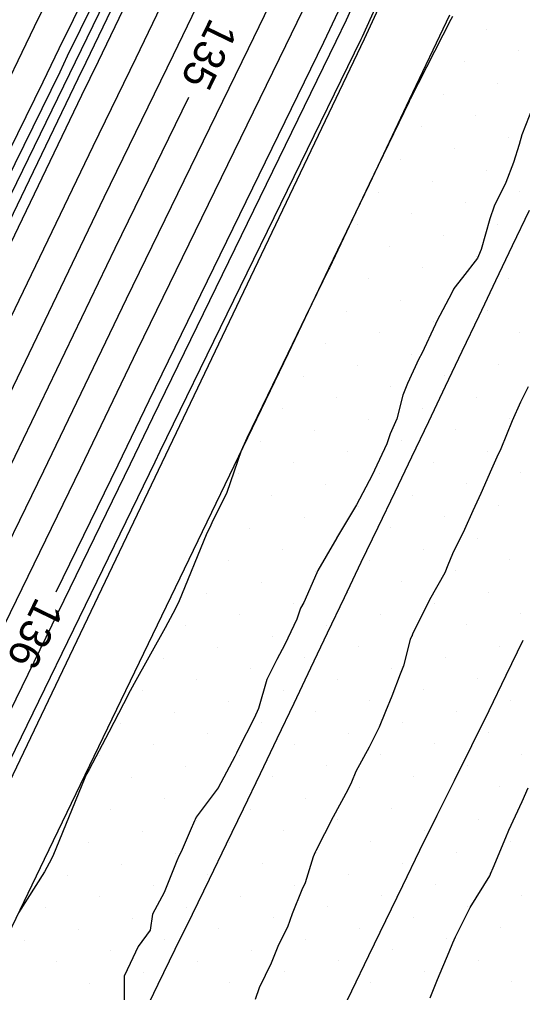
# Model space of a CAD drawing. Extents: x 2354170 to 2357230, y 866100 to 868290.
# Drawn here: x 2355371.3 to 2355403.5, y 866398.3 to 866460.6 of the extents above; entities that cross this region are included whole.
import ezdxf

# ---------------------------------------------------------------- set-up
doc = ezdxf.new("R2010")
doc.units = 0
for name, color, linetype in [('Default', 7, 'Continuous'), ('DTM Contours Major', 7, 'Continuous'), ('DTM Contours Major Text', 7, 'Continuous'), ('DTM Contours Minor', 7, 'Continuous'), ('Exist DTM Breakline', 7, 'Continuous'), ('Exist DTM Scan Elevation Point', 7, 'Continuous'), ('Exist Roads EOP', 7, 'Continuous'), ('PH Exist DTM Breakline', 7, 'Continuous')]:
    doc.layers.add(name, color=color, linetype=linetype)

msp = doc.modelspace()

# ---------------------------------------------------------------- linework, layer by layer
at = {"layer": 'Default'}
for points in [[(2355433.274, 866592.65), (2355424.806, 866571.951), (2355424.411, 866571.12), (2355422.868, 866571.668), (2355420.162, 866565.925), (2355419.736, 866563.735), (2355420.105, 866562.501), (2355413.621, 866548.376), (2355412.407, 866545.801), (2355402.074, 866526.578), (2355397.826, 866518.933), (2355392.022, 866504.988), (2355390.529, 866502.372), (2355387.356, 866494.737), (2355378.915, 866474.238), (2355377.709, 866471.334), (2355372.225, 866460.176), (2355369.578, 866454.696), (2355359.039, 866433.252), (2355357.778, 866430.64), (2355352.681, 866420.776), (2355349.804, 866415.162), (2355338.927, 866394.115), (2355337.24, 866390.821)], [(2355336.64, 866372.256), (2355339.663, 866378.549), (2355343.753, 866388.56), (2355346.394, 866394.067), (2355357.545, 866415.181), (2355357.799, 866415.7), (2355362.943, 866425.442), (2355365.741, 866431.183), (2355376.003, 866452.523), (2355378.759, 866458.177), (2355384.09, 866469.263), (2355386.61, 866474.85), (2355397.375, 866495.699), (2355400.619, 866502.876), (2355407.827, 866516.962), (2355410.624, 866522.841), (2355419.192, 866542.505), (2355426.718, 866555.797), (2355429.354, 866561.334), (2355429.604, 866563.56), (2355430.426, 866564.821), (2355431.528, 866567.132), (2355430.551, 866568.321), (2355442.375, 866586.643)], [(2355337.287, 866368.659), (2355341.828, 866378.112), (2355345.253, 866386.495), (2355349.543, 866395.439), (2355358.93, 866413.212), (2355359.335, 866414.044), (2355363.665, 866422.241), (2355368.111, 866431.366), (2355376.717, 866449.262), (2355381.159, 866458.376), (2355385.613, 866467.639), (2355389.708, 866476.715), (2355398.736, 866494.201), (2355403.429, 866504.581), (2355409.497, 866516.439), (2355413.331, 866524.5), (2355420.561, 866541.092), (2355426.912, 866552.308), (2355431.145, 866561.201), (2355431.357, 866563.085), (2355432.052, 866564.152), (2355433.804, 866567.826), (2355432.973, 866568.836), (2355443.028, 866584.416)], [(2355338.581, 866361.464), (2355346.158, 866377.236), (2355348.253, 866382.363), (2355355.841, 866398.182), (2355361.699, 866409.275), (2355362.409, 866410.731), (2355365.108, 866415.841), (2355372.851, 866431.732), (2355378.145, 866442.741), (2355385.959, 866458.773), (2355388.661, 866464.392), (2355395.902, 866480.443), (2355401.46, 866491.207), (2355409.048, 866507.992), (2355412.835, 866515.394), (2355418.746, 866527.817), (2355423.299, 866538.266), (2355427.298, 866545.329), (2355434.727, 866560.935), (2355434.862, 866562.135), (2355435.305, 866562.815), (2355438.356, 866569.213), (2355437.818, 866569.868), (2355444.332, 866579.962)], [(2355406.465, 866530.834), (2355402.54, 866523.532), (2355399.868, 866518.725), (2355393.049, 866502.339), (2355392.222, 866500.891), (2355390.465, 866496.663), (2355380.621, 866472.756), (2355380.168, 866471.665), (2355373.822, 866458.755), (2355372.795, 866456.627), (2355364.665, 866440.085)], [(2355416.208, 866514.42), (2355416.174, 866514.348), (2355414.668, 866511.403), (2355404.183, 866488.212), (2355402.097, 866484.172), (2355391.708, 866461.146), (2355390.759, 866459.171), (2355379.573, 866436.22), (2355377.591, 866432.097), (2355373.624, 866423.956)], [(2355405.194, 866486.036), (2355393.232, 866459.522), (2355393.159, 866459.369), (2355380.287, 866432.959), (2355379.961, 866432.28), (2355367.272, 866406.241), (2355367.019, 866405.761), (2355365.854, 866403.37), (2355365.287, 866402.297), (2355352.753, 866376.167), (2355352.653, 866375.923), (2355341.387, 866352.472), (2355340.659, 866350.872), (2355340.623, 866350.802), (2355340.589, 866350.736), (2355340.557, 866350.674), (2355340.528, 866350.607), (2355340.495, 866350.531), (2355331.001, 866327.562)], [(2355336.417, 866351.091), (2355339.228, 866357.866), (2355348.323, 866376.799), (2355349.753, 866380.298), (2355358.989, 866399.554), (2355363.084, 866407.307), (2355363.946, 866409.074), (2355365.829, 866412.641), (2355375.221, 866431.914), (2355378.859, 866439.481), (2355388.359, 866458.972), (2355390.184, 866462.769)], [(2355334.401, 866372.018), (2355335.993, 866375.854), (2355337.498, 866378.987), (2355342.253, 866390.626), (2355343.246, 866392.695), (2355356.16, 866417.149), (2355356.262, 866417.357), (2355362.221, 866428.642), (2355363.371, 866431), (2355375.289, 866455.784), (2355376.359, 866457.979), (2355378.218, 866461.844)], [(2355399.022, 866460.838), (2355398.921, 866460.632), (2355396.309, 866455.526), (2355396.293, 866455.496), (2355396.273, 866455.455), (2355396.24, 866455.379), (2355394.259, 866451.292), (2355393.678, 866450.087), (2355392.398, 866447.393), (2355391.138, 866444.731), (2355391.102, 866444.657), (2355391.097, 866444.646), (2355391.09, 866444.631), (2355389.617, 866441.586), (2355388.485, 866439.24), (2355385.844, 866433.828), (2355385.496, 866433.015), (2355384.563, 866430.346), (2355383.61, 866428.394), (2355383.479, 866428.103), (2355383.291, 866427.726), (2355381.476, 866423.294), (2355381.122, 866422.597), (2355380.623, 866421.676), (2355378.638, 866418.108), (2355378.389, 866417.632), (2355377.958, 866416.807), (2355377.011, 866414.986), (2355375.746, 866412.595), (2355375.55, 866412.222), (2355375.518, 866412.158), (2355375.478, 866412.071), (2355373.427, 866407.034), (2355373.195, 866406.6), (2355372.892, 866406.042), (2355371.232, 866403.418)], [(2355338.298, 866365.818), (2355343.993, 866377.674), (2355346.753, 866384.429), (2355352.692, 866396.81), (2355360.315, 866411.244), (2355360.872, 866412.387), (2355364.386, 866419.041), (2355370.481, 866431.549), (2355377.431, 866446.002), (2355382.14, 866455.663)], [(2355404.172, 866455.045), (2355403.459, 866453.255), (2355403.287, 866452.633), (2355402.935, 866451.485), (2355402.45, 866450.189), (2355401.702, 866448.677), (2355401.415, 866447.876), (2355400.857, 866445.901), (2355400.697, 866445.491), (2355400.631, 866445.355), (2355399.667, 866444.103), (2355399.111, 866443.406), (2355399.083, 866443.343), (2355398.783, 866442.767), (2355398.032, 866441.308), (2355397.944, 866441.129), (2355397.064, 866439.234), (2355396.866, 866438.896), (2355396.144, 866437.332), (2355395.846, 866436.573), (2355395.457, 866435.051), (2355395.041, 866434.108), (2355394.816, 866433.454), (2355394.03, 866431.779), (2355393.877, 866431.458), (2355392.873, 866429.547), (2355391.6, 866427.415), (2355391.592, 866427.397), (2355391.473, 866427.187), (2355390.405, 866425.337), (2355390.342, 866425.199), (2355389.497, 866423.296), (2355389.286, 866422.928), (2355389.048, 866422.228), (2355388.279, 866420.596), (2355387.77, 866419.646), (2355387.141, 866418.351), (2355386.605, 866416.507), (2355386.333, 866415.888), (2355385.329, 866413.914), (2355385.189, 866413.647), (2355385.08, 866413.43), (2355384.027, 866411.418), (2355382.613, 866409.535), (2355382.553, 866409.396), (2355382.497, 866409.296), (2355382.22, 866408.671), (2355381.651, 866407.31), (2355381.524, 866407.079), (2355381.377, 866406.748), (2355380.556, 866404.722), (2355379.803, 866403.335), (2355379.67, 866402.311), (2355378.888, 866401.25), (2355378.382, 866400.165), (2355378.004, 866399.361), (2355377.992, 866397.749)]]:
    msp.add_lwpolyline(points, dxfattribs=at)
at = {"layer": 'DTM Contours Major'}
msp.add_lwpolyline([(2355338.298, 866365.818), (2355343.993, 866377.674), (2355346.753, 866384.429), (2355352.692, 866396.81), (2355360.315, 866411.244), (2355360.872, 866412.387), (2355364.386, 866419.041), (2355370.481, 866431.549), (2355377.431, 866446.002), (2355382.14, 866455.663)], dxfattribs=at)
at = {"layer": 'DTM Contours Minor'}
for points in [[(2355399.763, 866516.766), (2355393.392, 866501.457), (2355392.787, 866500.397), (2355391.502, 866497.306), (2355381.19, 866472.262), (2355380.988, 866471.775), (2355374.355, 866458.281), (2355373.867, 866457.271), (2355361.144, 866431.383), (2355360.874, 866430.823), (2355354.726, 866418.925), (2355354.15, 866417.801), (2355340.943, 866392.246), (2355340.66, 866391.694), (2355334.233, 866380.026), (2355333.119, 866377.75), (2355319.997, 866353.661), (2355315.443, 866345.205), (2355313.17, 866340.539), (2355311.526, 866337.459)], [(2355407.018, 866492.981), (2355404.637, 866487.713), (2355403.129, 866484.793), (2355392.216, 866460.604), (2355391.559, 866459.237), (2355379.811, 866435.133), (2355378.381, 866432.158), (2355366.791, 866408.374), (2355365.995, 866406.866), (2355364.93, 866404.683), (2355363.188, 866401.383), (2355351.753, 866377.544), (2355351.21, 866376.215), (2355340.091, 866353.07), (2355339.164, 866350.837), (2355338.86, 866350.045), (2355327.207, 866324.238), (2355326.871, 866323.38), (2355321.752, 866312.104)], [(2355308.331, 866310.232), (2355311.374, 866316.937), (2355319.426, 866337.506), (2355322.028, 866343.268), (2355325.427, 866352.109), (2355335.777, 866377.053), (2355336.776, 866379.133), (2355341.753, 866391.314), (2355342.196, 866392.238), (2355355.699, 866417.805), (2355355.75, 866417.909), (2355361.981, 866429.708), (2355362.581, 866430.939), (2355375.051, 866456.87), (2355375.559, 866457.912), (2355382.058, 866471.427), (2355382.481, 866472.365), (2355392.371, 866491.519)], [(2355403.874, 866437.102), (2355403.379, 866436.122), (2355402.851, 866434.936), (2355402.12, 866433.137), (2355401.856, 866432.596), (2355401.526, 866431.828), (2355400.833, 866430.276), (2355400.326, 866429.164), (2355399.792, 866427.967), (2355399.022, 866426.403), (2355398.727, 866425.674), (2355398.539, 866425.192), (2355397.543, 866423.46), (2355396.462, 866421.259), (2355396.434, 866421.196), (2355396.317, 866420.917), (2355395.883, 866419.239), (2355395.673, 866418.701), (2355395.133, 866417.282), (2355394.742, 866416.32), (2355394.32, 866415.312), (2355393.69, 866414.018), (2355392.84, 866412.467), (2355392.547, 866411.777), (2355392.322, 866411.297), (2355391.378, 866409.553), (2355390.268, 866407.379), (2355390.24, 866407.308), (2355390.106, 866406.997), (2355389.583, 866405.327), (2355389.379, 866404.88), (2355388.765, 866403.357), (2355388.458, 866402.492), (2355387.884, 866401.371), (2355387.406, 866400.19), (2355386.641, 866398.613), (2355386.393, 866397.863)], [(2355397.596, 866397.975), (2355398.058, 866399.138), (2355398.802, 866400.911), (2355399.036, 866401.489), (2355399.211, 866401.876), (2355400.153, 866403.747), (2355401.416, 866405.793), (2355401.46, 866405.88), (2355401.485, 866405.947), (2355401.627, 866406.288), (2355402.433, 866408.234), (2355402.627, 866408.706), (2355403.485, 866410.536), (2355403.876, 866411.427)]]:
    msp.add_lwpolyline(points, dxfattribs=at)
at = {"layer": 'Exist DTM Breakline'}
for points in [[(2355379.083, 866396.585), (2355380.175, 866398.833), (2355381.272, 866401.08), (2355382.368, 866403.327), (2355383.464, 866405.574), (2355384.557, 866407.822), (2355385.638, 866410.076), (2355386.719, 866412.331), (2355387.8, 866414.585), (2355388.88, 866416.84), (2355389.955, 866419.097), (2355391.03, 866421.354), (2355392.105, 866423.611), (2355393.181, 866425.867), (2355394.262, 866428.121), (2355395.343, 866430.376), (2355396.424, 866432.63), (2355397.503, 866434.885), (2355398.577, 866437.142), (2355399.651, 866439.4), (2355400.725, 866441.657), (2355401.8, 866443.915), (2355402.877, 866446.171), (2355403.954, 866448.427)], [(2355391.48, 866396.171), (2355392.57, 866398.421), (2355393.661, 866400.67), (2355394.751, 866402.92), (2355395.842, 866405.17), (2355396.932, 866407.419), (2355398.039, 866409.661), (2355399.152, 866411.9), (2355400.264, 866414.138), (2355401.374, 866416.378), (2355402.459, 866418.631), (2355403.543, 866420.884)]]:
    msp.add_lwpolyline(points, dxfattribs=at)
at = {"layer": 'Exist DTM Scan Elevation Point'}
for p, q in [((2355401.198, 866460.01), (2355401.198, 866460.01)), ((2355403.283, 866458.631), (2355403.283, 866458.631)), ((2355399.819, 866457.925), (2355399.819, 866457.925)), ((2355401.904, 866456.546), (2355401.904, 866456.546)), ((2355398.439, 866455.84), (2355398.439, 866455.84)), ((2355400.524, 866454.461), (2355400.524, 866454.461)), ((2355397.06, 866453.755), (2355397.06, 866453.755)), ((2355402.609, 866453.082), (2355402.609, 866453.082)), ((2355399.145, 866452.376), (2355399.145, 866452.376)), ((2355395.681, 866451.67), (2355395.681, 866451.67)), ((2355401.23, 866450.997), (2355401.23, 866450.997)), ((2355397.766, 866450.291), (2355397.766, 866450.291)), ((2355394.301, 866449.585), (2355394.301, 866449.585)), ((2355403.315, 866449.617), (2355403.315, 866449.617)), ((2355399.851, 866448.912), (2355399.851, 866448.912)), ((2355396.386, 866448.206), (2355396.386, 866448.206)), ((2355392.922, 866447.5), (2355392.922, 866447.5)), ((2355401.936, 866447.532), (2355401.936, 866447.532)), ((2355398.471, 866446.827), (2355398.471, 866446.827)), ((2355395.007, 866446.121), (2355395.007, 866446.121)), ((2355400.556, 866445.447), (2355400.556, 866445.447)), ((2355397.092, 866444.742), (2355397.092, 866444.742)), ((2355393.627, 866444.036), (2355393.627, 866444.036)), ((2355402.641, 866444.068), (2355402.641, 866444.068)), ((2355399.177, 866443.362), (2355399.177, 866443.362)), ((2355395.712, 866442.657), (2355395.712, 866442.657)), ((2355392.248, 866441.951), (2355392.248, 866441.951)), ((2355401.262, 866441.983), (2355401.262, 866441.983)), ((2355397.797, 866441.277), (2355397.797, 866441.277)), ((2355394.333, 866440.572), (2355394.333, 866440.572)), ((2355403.347, 866440.603), (2355403.347, 866440.603)), ((2355390.868, 866439.866), (2355390.868, 866439.866)), ((2355396.418, 866439.192), (2355396.418, 866439.192)), ((2355401.967, 866438.518), (2355401.967, 866438.518)), ((2355392.953, 866438.487), (2355392.953, 866438.487)), ((2355389.489, 866437.781), (2355389.489, 866437.781)), ((2355398.503, 866437.813), (2355398.503, 866437.813)), ((2355395.038, 866437.107), (2355395.038, 866437.107)), ((2355391.574, 866436.402), (2355391.574, 866436.402)), ((2355400.588, 866436.433), (2355400.588, 866436.433)), ((2355388.11, 866435.696), (2355388.11, 866435.696)), ((2355397.123, 866435.728), (2355397.123, 866435.728)), ((2355393.659, 866435.022), (2355393.659, 866435.022)), ((2355402.673, 866435.054), (2355402.673, 866435.054)), ((2355390.195, 866434.317), (2355390.195, 866434.317)), ((2355399.208, 866434.348), (2355399.208, 866434.348)), ((2355386.73, 866433.611), (2355386.73, 866433.611)), ((2355395.744, 866433.643), (2355395.744, 866433.643)), ((2355392.28, 866432.937), (2355392.28, 866432.937)), ((2355401.293, 866432.969), (2355401.293, 866432.969)), ((2355388.815, 866432.232), (2355388.815, 866432.232)), ((2355397.829, 866432.263), (2355397.829, 866432.263)), ((2355385.351, 866431.526), (2355385.351, 866431.526)), ((2355394.364, 866431.558), (2355394.364, 866431.558)), ((2355403.378, 866431.589), (2355403.378, 866431.589)), ((2355390.9, 866430.852), (2355390.9, 866430.852)), ((2355399.914, 866430.884), (2355399.914, 866430.884)), ((2355387.436, 866430.147), (2355387.436, 866430.147)), ((2355396.449, 866430.178), (2355396.449, 866430.178)), ((2355392.985, 866429.473), (2355392.985, 866429.473)), ((2355401.999, 866429.504), (2355401.999, 866429.504)), ((2355389.521, 866428.767), (2355389.521, 866428.767)), ((2355398.534, 866428.799), (2355398.534, 866428.799)), ((2355386.056, 866428.062), (2355386.056, 866428.062)), ((2355395.07, 866428.093), (2355395.07, 866428.093)), ((2355391.606, 866427.388), (2355391.606, 866427.388)), ((2355400.619, 866427.419), (2355400.619, 866427.419)), ((2355388.141, 866426.682), (2355388.141, 866426.682)), ((2355397.155, 866426.714), (2355397.155, 866426.714)), ((2355384.677, 866425.977), (2355384.677, 866425.977)), ((2355393.691, 866426.008), (2355393.691, 866426.008)), ((2355402.704, 866426.04), (2355402.704, 866426.04)), ((2355390.226, 866425.303), (2355390.226, 866425.303)), ((2355399.24, 866425.334), (2355399.24, 866425.334)), ((2355386.762, 866424.597), (2355386.762, 866424.597)), ((2355395.776, 866424.629), (2355395.776, 866424.629)), ((2355383.297, 866423.892), (2355383.297, 866423.892)), ((2355392.311, 866423.923), (2355392.311, 866423.923)), ((2355401.325, 866423.955), (2355401.325, 866423.955)), ((2355388.847, 866423.218), (2355388.847, 866423.218)), ((2355397.861, 866423.249), (2355397.861, 866423.249)), ((2355385.382, 866422.512), (2355385.382, 866422.512)), ((2355394.396, 866422.544), (2355394.396, 866422.544)), ((2355403.41, 866422.576), (2355403.41, 866422.576)), ((2355381.918, 866421.807), (2355381.918, 866421.807)), ((2355390.932, 866421.838), (2355390.932, 866421.838)), ((2355399.946, 866421.87), (2355399.946, 866421.87)), ((2355387.467, 866421.133), (2355387.467, 866421.133)), ((2355396.481, 866421.165), (2355396.481, 866421.165)), ((2355393.017, 866420.459), (2355393.017, 866420.459)), ((2355402.031, 866420.491), (2355402.031, 866420.491)), ((2355384.003, 866420.427), (2355384.003, 866420.427)), ((2355380.539, 866419.722), (2355380.539, 866419.722)), ((2355389.552, 866419.753), (2355389.552, 866419.753)), ((2355398.566, 866419.785), (2355398.566, 866419.785)), ((2355386.088, 866419.048), (2355386.088, 866419.048)), ((2355395.102, 866419.08), (2355395.102, 866419.08)), ((2355382.623, 866418.342), (2355382.623, 866418.342)), ((2355391.637, 866418.374), (2355391.637, 866418.374)), ((2355400.651, 866418.406), (2355400.651, 866418.406)), ((2355379.159, 866417.637), (2355379.159, 866417.637)), ((2355388.173, 866417.668), (2355388.173, 866417.668)), ((2355397.187, 866417.7), (2355397.187, 866417.7)), ((2355384.708, 866416.963), (2355384.708, 866416.963)), ((2355393.722, 866416.995), (2355393.722, 866416.995)), ((2355402.736, 866417.026), (2355402.736, 866417.026)), ((2355381.244, 866416.257), (2355381.244, 866416.257)), ((2355390.258, 866416.289), (2355390.258, 866416.289)), ((2355399.272, 866416.321), (2355399.272, 866416.321)), ((2355377.78, 866415.552), (2355377.78, 866415.552)), ((2355386.793, 866415.583), (2355386.793, 866415.583)), ((2355395.807, 866415.615), (2355395.807, 866415.615)), ((2355383.329, 866414.878), (2355383.329, 866414.878)), ((2355392.343, 866414.91), (2355392.343, 866414.91)), ((2355401.357, 866414.941), (2355401.357, 866414.941)), ((2355388.878, 866414.204), (2355388.878, 866414.204)), ((2355397.892, 866414.236), (2355397.892, 866414.236)), ((2355379.865, 866414.172), (2355379.865, 866414.172)), ((2355376.4, 866413.467), (2355376.4, 866413.467)), ((2355385.414, 866413.498), (2355385.414, 866413.498)), ((2355394.428, 866413.53), (2355394.428, 866413.53)), ((2355403.442, 866413.562), (2355403.442, 866413.562)), ((2355381.95, 866412.793), (2355381.95, 866412.793)), ((2355390.963, 866412.825), (2355390.963, 866412.825)), ((2355399.977, 866412.856), (2355399.977, 866412.856)), ((2355378.485, 866412.087), (2355378.485, 866412.087)), ((2355387.499, 866412.119), (2355387.499, 866412.119)), ((2355396.513, 866412.151), (2355396.513, 866412.151)), ((2355384.035, 866411.413), (2355384.035, 866411.413)), ((2355393.048, 866411.445), (2355393.048, 866411.445)), ((2355402.062, 866411.477), (2355402.062, 866411.477)), ((2355380.57, 866410.708), (2355380.57, 866410.708)), ((2355389.584, 866410.74), (2355389.584, 866410.74)), ((2355377.106, 866410.002), (2355377.106, 866410.002)), ((2355386.12, 866410.034), (2355386.12, 866410.034)), ((2355395.133, 866410.066), (2355395.133, 866410.066)), ((2355382.655, 866409.328), (2355382.655, 866409.328)), ((2355391.669, 866409.36), (2355391.669, 866409.36)), ((2355400.683, 866409.392), (2355400.683, 866409.392)), ((2355379.191, 866408.623), (2355379.191, 866408.623)), ((2355388.205, 866408.655), (2355388.205, 866408.655)), ((2355397.218, 866408.686), (2355397.218, 866408.686)), ((2355393.754, 866407.981), (2355393.754, 866407.981)), ((2355402.768, 866408.012), (2355402.768, 866408.012)), ((2355375.726, 866407.917), (2355375.726, 866407.917)), ((2355384.74, 866407.949), (2355384.74, 866407.949)), ((2355381.276, 866407.243), (2355381.276, 866407.243)), ((2355390.29, 866407.275), (2355390.29, 866407.275)), ((2355399.303, 866407.307), (2355399.303, 866407.307)), ((2355377.811, 866406.538), (2355377.811, 866406.538)), ((2355386.825, 866406.57), (2355386.825, 866406.57)), ((2355395.839, 866406.601), (2355395.839, 866406.601)), ((2355374.347, 866405.832), (2355374.347, 866405.832)), ((2355383.361, 866405.864), (2355383.361, 866405.864)), ((2355392.375, 866405.896), (2355392.375, 866405.896)), ((2355401.388, 866405.927), (2355401.388, 866405.927)), ((2355379.896, 866405.158), (2355379.896, 866405.158)), ((2355388.91, 866405.19), (2355388.91, 866405.19)), ((2355397.924, 866405.222), (2355397.924, 866405.222)), ((2355376.432, 866404.453), (2355376.432, 866404.453)), ((2355385.446, 866404.485), (2355385.446, 866404.485)), ((2355394.46, 866404.516), (2355394.46, 866404.516)), ((2355403.473, 866404.548), (2355403.473, 866404.548)), ((2355372.967, 866403.747), (2355372.967, 866403.747)), ((2355381.981, 866403.779), (2355381.981, 866403.779)), ((2355390.995, 866403.811), (2355390.995, 866403.811)), ((2355400.009, 866403.842), (2355400.009, 866403.842)), ((2355378.517, 866403.074), (2355378.517, 866403.074)), ((2355387.531, 866403.105), (2355387.531, 866403.105)), ((2355396.545, 866403.137), (2355396.545, 866403.137)), ((2355375.052, 866402.368), (2355375.052, 866402.368)), ((2355384.066, 866402.4), (2355384.066, 866402.4)), ((2355393.08, 866402.431), (2355393.08, 866402.431)), ((2355402.094, 866402.463), (2355402.094, 866402.463)), ((2355398.63, 866401.757), (2355398.63, 866401.757)), ((2355371.588, 866401.662), (2355371.588, 866401.662)), ((2355380.602, 866401.694), (2355380.602, 866401.694)), ((2355389.616, 866401.726), (2355389.616, 866401.726)), ((2355377.137, 866400.989), (2355377.137, 866400.989)), ((2355386.151, 866401.02), (2355386.151, 866401.02)), ((2355395.165, 866401.052), (2355395.165, 866401.052)), ((2355373.673, 866400.283), (2355373.673, 866400.283)), ((2355382.687, 866400.315), (2355382.687, 866400.315)), ((2355391.701, 866400.346), (2355391.701, 866400.346)), ((2355400.714, 866400.378), (2355400.714, 866400.378)), ((2355379.222, 866399.609), (2355379.222, 866399.609)), ((2355388.236, 866399.641), (2355388.236, 866399.641)), ((2355397.25, 866399.672), (2355397.25, 866399.672)), ((2355375.758, 866398.904), (2355375.758, 866398.904)), ((2355384.772, 866398.935), (2355384.772, 866398.935)), ((2355393.786, 866398.967), (2355393.786, 866398.967)), ((2355402.799, 866398.999), (2355402.799, 866398.999))]:
    msp.add_line(p, q, dxfattribs=at)
at = {"layer": 'Exist Roads EOP'}
msp.add_lwpolyline([(2355398.828, 866460.912), (2355396.257, 866455.49), (2355393.678, 866450.073), (2355391.091, 866444.659), (2355388.496, 866439.249), (2355385.895, 866433.842), (2355383.29, 866428.438), (2355380.682, 866423.034), (2355378.075, 866417.63), (2355375.469, 866412.226), (2355372.866, 866406.819), (2355370.268, 866401.411), (2355367.672, 866396.002), (2355365.077, 866390.592), (2355362.481, 866385.183), (2355359.882, 866379.775), (2355357.279, 866374.369), (2355354.671, 866368.965), (2355352.059, 866363.564)], dxfattribs=at)
at = {"layer": 'PH Exist DTM Breakline'}
for points in [[(2355493.481, 866667.653), (2355482.335, 866644.759), (2355460.278, 866598.533), (2355441.015, 866560.468), (2355418.38, 866513.657), (2355393.36, 866459.386), (2355366.298, 866402.738), (2355340.515, 866350.712), (2355316.886, 866301.426), (2355305.28, 866277.599)], [(2355281.117, 866263.09), (2355291.385, 866283.678), (2355294.507, 866291.064), (2355304.567, 866314.107), (2355322.328, 866352.396), (2355341.35, 866391.869), (2355361.718, 866430.873), (2355381.648, 866471.864), (2355403.329, 866518.372), (2355424.612, 866562.24), (2355423.403, 866563.319), (2355423.174, 866564.881), (2355424.474, 866567.914), (2355426.326, 866567.421), (2355427.666, 866565.955), (2355427.962, 866564.005), (2355426.4, 866561.553)]]:
    msp.add_lwpolyline(points, dxfattribs=at)

# ---------------------------------------------------------------- texts
at = {"layer": 'Default'}
for s, rotation, p in [('135', 244.15599, (2355383.532, 866460.816)), ('136', 244.02151, (2355372.394, 866423.715))]:
    msp.add_text(s, height=2, rotation=rotation, dxfattribs=at).set_placement(p)
at = {"layer": 'DTM Contours Major Text'}
msp.add_text('135', height=2, rotation=244.15599, dxfattribs=at).set_placement((2355383.532, 866460.816))

doc.saveas('drawing.dxf')
